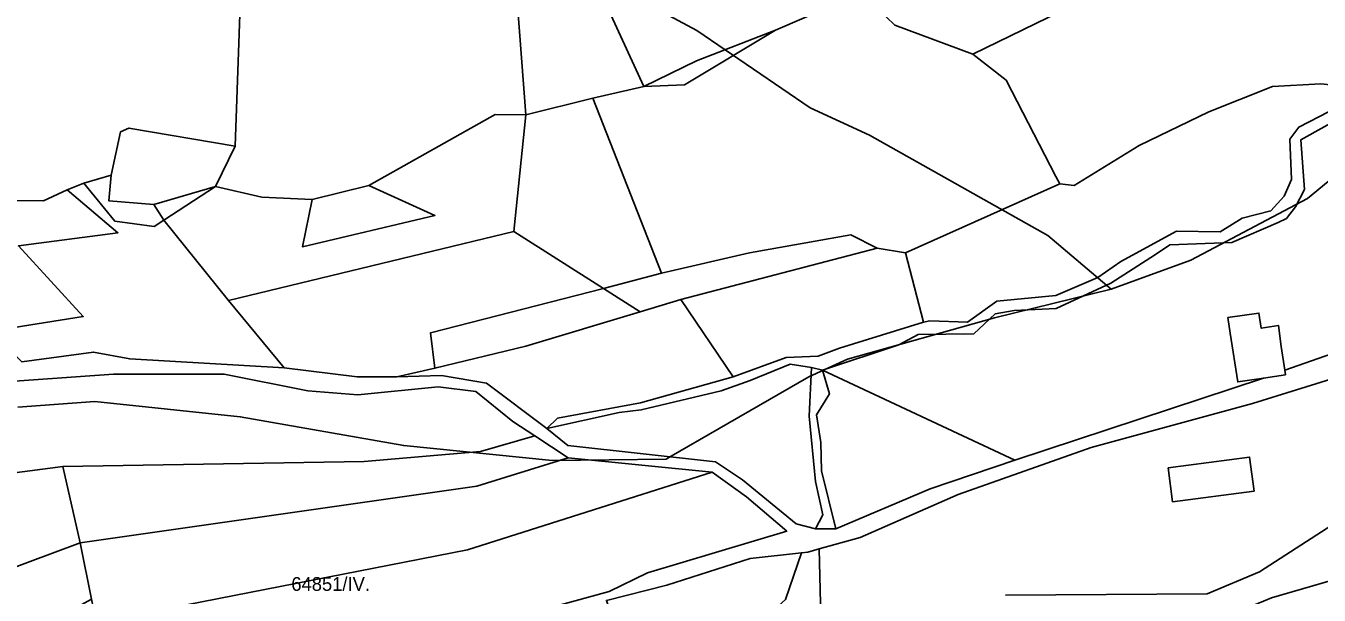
# Model space of a CAD drawing. Extents: x -521261 to -517465, y -1182764 to -1179456.
# Drawn here: x -520234.1 to -519763.3, y -1181096.5 to -1180889.1 of the extents above; entities that cross this region are included whole.
import ezdxf

# ---------------------------------------------------------------- set-up
doc = ezdxf.new("R2010")
doc.units = 0
for name, color, linetype in [('95610013', 7, 'Continuous'), ('95620013', 7, 'Continuous'), ('95630013', 7, 'Continuous'), ('95640013', 7, 'Continuous'), ('95660013', 7, 'Continuous')]:
    doc.layers.add(name, color=color, linetype=linetype)

msp = doc.modelspace()

# ---------------------------------------------------------------- linework, layer by layer
at = {"layer": '95610013'}
for points in [[(-520212.94, -1180946.42), (-520202.96, -1180943.49), (-520203.9, -1180952.83), (-520187.42, -1180954.15), (-520183.85, -1180959.97), (-520187.3, -1180962.26), (-520201.71, -1180960.23)], [(-520260.64, -1180952.48), (-520227.61, -1180952.85), (-520219.04, -1180948.87), (-520200.55, -1180964.48), (-520236.79, -1180969.29), (-520213.15, -1180995.05), (-520246.78, -1181000.33), (-520278.88, -1180969.13), (-520300.29, -1180947.88)], [(-520212.94, -1180946.42), (-520201.71, -1180960.23), (-520187.3, -1180962.26), (-520183.85, -1180959.97), (-520160.25, -1180989.16), (-520140.01, -1181013.64), (-520196.24, -1181010.47), (-520209.39, -1181007.96), (-520235.48, -1181011.57), (-520246.78, -1181000.33), (-520213.15, -1180995.05), (-520236.79, -1180969.29), (-520200.55, -1180964.48), (-520219.04, -1180948.87)], [(-519995.59, -1180988.79), (-519976.54, -1181017.03), (-520010.31, -1181026.46), (-520040.52, -1181031.99), (-520044.41, -1181035.77), (-520066.38, -1181019.3), (-520082.79, -1181016.48), (-520099.06, -1181016.94), (-520085.14, -1181013.84), (-520052.02, -1181005.79), (-520010.45, -1180993.34)], [(-519948.04, -1181013.6), (-519948.9, -1181031.28), (-519946.67, -1181055.07), (-519943.89, -1181067.29), (-519946.57, -1181072.34), (-519953.68, -1181070.49), (-519973.14, -1181054.48), (-519982.97, -1181047.91), (-520036.74, -1181042.02), (-520044.41, -1181035.77), (-520018.1, -1181030.01), (-520010.05, -1181029.02), (-519980.97, -1181022.1), (-519970.37, -1181018.3), (-519955.79, -1181012.41)], [(-519944.01, -1181014.53), (-519874, -1181047.31), (-519904.93, -1181057.82), (-519939.24, -1181072.38), (-519944.44, -1181051.2), (-519944.65, -1181040.94), (-519946.23, -1181030.81), (-519941.52, -1181023.22)], [(-519739.3, -1181085.44), (-519712.94, -1181129.93), (-519700.84, -1181149.53), (-519735.12, -1181160.39), (-519742.39, -1181165.26), (-519775.16, -1181167.72), (-519803.6, -1181180.37), (-519840.89, -1181127.16), (-519809.28, -1181109.36), (-519780.6, -1181097.51)]]:
    msp.add_lwpolyline(points, close=True, dxfattribs=at)
at = {"layer": '95620013'}
for points in [[(-520153.4, -1180806.35), (-520157.92, -1180932.93), (-520196.52, -1180926.36), (-520199.57, -1180927.79), (-520202.96, -1180943.49), (-520212.94, -1180946.42), (-520219.04, -1180948.87), (-520227.61, -1180952.85), (-520260.64, -1180952.48), (-520300.29, -1180947.88), (-520344.99, -1180950.96), (-520344.3, -1180943.96), (-520347.18, -1180922.08), (-520360, -1180918.29), (-520377.28, -1180904.27), (-520373.63, -1180892.94), (-520376.27, -1180881.41), (-520440.58, -1180853.57), (-520296.21, -1180829.93)], [(-520199.57, -1180927.79), (-520196.52, -1180926.36), (-520157.92, -1180932.93), (-520165.05, -1180947.64), (-520187.42, -1180954.15), (-520203.9, -1180952.83), (-520202.96, -1180943.49)]]:
    msp.add_lwpolyline(points, close=True, dxfattribs=at)
at = {"layer": '95630013'}
msp.add_lwpolyline([(-519752.96, -1180921.13), (-519769.89, -1180930.62), (-519768.62, -1180948.73), (-519771.88, -1180955.04), (-519775.19, -1180959.33), (-519778.17, -1180960.73), (-519795.09, -1180968.03), (-519817.61, -1180968.87), (-519822.81, -1180972.36), (-519839.07, -1180982.9), (-519859, -1180992.12), (-519874.24, -1180992.85), (-519881.2, -1180994.07), (-519889.01, -1181001.36), (-519909.19, -1181001.61), (-519916.32, -1181005.27), (-519944.01, -1181014.53), (-519948.04, -1181013.6), (-519955.79, -1181012.41), (-519970.37, -1181018.3), (-519980.97, -1181022.1), (-520010.05, -1181029.02), (-520018.1, -1181030.01), (-520044.41, -1181035.77), (-520040.52, -1181031.99), (-520010.31, -1181026.46), (-519976.54, -1181017.03), (-519957.3, -1181009.97), (-519945.7, -1181009.39), (-519937.88, -1181006.53), (-519907.35, -1180997.12), (-519905.05, -1180996.64), (-519891.34, -1180997.12), (-519880.65, -1180989.37), (-519859.13, -1180987.38), (-519843.84, -1180980.85), (-519835.41, -1180974.97), (-519815.24, -1180963.96), (-519799.37, -1180964.18), (-519791.36, -1180959.21), (-519780.85, -1180956.47), (-519776, -1180951.23), (-519773.4, -1180945.12), (-519773.93, -1180930.43), (-519770.71, -1180926.01), (-519756.06, -1180918.46)], dxfattribs=at)
for points in [[(-519944.01, -1181014.53), (-519941.52, -1181023.22), (-519946.23, -1181030.81), (-519944.65, -1181040.94), (-519944.44, -1181051.2), (-519939.24, -1181072.38), (-519942.24, -1181072.32), (-519946.57, -1181072.34), (-519943.89, -1181067.29), (-519946.67, -1181055.07), (-519948.9, -1181031.28), (-519948.04, -1181013.6)], [(-519970.42, -1181083.14), (-519951.75, -1181081.08), (-519957.49, -1181098.06), (-519974.19, -1181113.01), (-519981.67, -1181128.85), (-520009.75, -1181138.53), (-520022.75, -1181098.44), (-520000.75, -1181092.9)], [(-519949.41, -1181080.84), (-519945.25, -1181079.6), (-519944.34, -1181119.43), (-519981.67, -1181128.85), (-519974.19, -1181113.01), (-519957.49, -1181098.06), (-519951.75, -1181081.08)]]:
    msp.add_lwpolyline(points, close=True, dxfattribs=at)
at = {"layer": '95640013'}
for points in [[(-520075.86, -1180795.03), (-520062.43, -1180839.83), (-520055.89, -1180870.36), (-520052.08, -1180921.54), (-520063.22, -1180921.42), (-520109.27, -1180947.28), (-520129.83, -1180952.33), (-520148.15, -1180951.58), (-520165.05, -1180947.64), (-520157.92, -1180932.93), (-520153.4, -1180806.35)], [(-520075.86, -1180795.03), (-520054.72, -1180801.07), (-520044.44, -1180834.39), (-520009.14, -1180911.27), (-520027.64, -1180915.53), (-520052.08, -1180921.54), (-520055.89, -1180870.36), (-520062.43, -1180839.83)], [(-519944.79, -1180803.65), (-519895.53, -1180797.23), (-519830.34, -1180816.46), (-519820.97, -1180866.09), (-519889.4, -1180899.42), (-519917.75, -1180888.83), (-519929.88, -1180877.1), (-519932.71, -1180837.71), (-519936.58, -1180818.81)], [(-519957.95, -1180803.28), (-519944.79, -1180803.65), (-519936.58, -1180818.81), (-519932.71, -1180837.71), (-519929.88, -1180877.1), (-519961.16, -1180890.66), (-519989.88, -1180901.85), (-520009.14, -1180911.27), (-520044.44, -1180834.39), (-520054.72, -1180801.07), (-520000.15, -1180806.24)], [(-519917.75, -1180888.83), (-519889.4, -1180899.42), (-519877.24, -1180908.93), (-519859.11, -1180944.04), (-519857.68, -1180946.63), (-519913.83, -1180971.76), (-519924.17, -1180970.12), (-519933.74, -1180965.29), (-519970.64, -1180971.8), (-520002.63, -1180979.16), (-520027.64, -1180915.53), (-520009.14, -1180911.27), (-519994.33, -1180910.58), (-519961.16, -1180890.66), (-519929.88, -1180877.1)], [(-519989.88, -1180901.85), (-519961.16, -1180890.66), (-519994.33, -1180910.58), (-520009.14, -1180911.27)], [(-519780.23, -1180911.25), (-519762.65, -1180910.2), (-519750.97, -1180911.49), (-519756.06, -1180918.46), (-519770.71, -1180926.01), (-519773.93, -1180930.43), (-519773.4, -1180945.12), (-519776, -1180951.23), (-519780.85, -1180956.47), (-519791.36, -1180959.21), (-519799.37, -1180964.18), (-519815.24, -1180963.96), (-519835.41, -1180974.97), (-519843.84, -1180980.85), (-519859.13, -1180987.38), (-519880.65, -1180989.37), (-519891.34, -1180997.12), (-519905.05, -1180996.64), (-519907.35, -1180997.12), (-519913.83, -1180971.76), (-519857.68, -1180946.63), (-519852.45, -1180947.32), (-519828.85, -1180932.73), (-519803.42, -1180920.5)], [(-520052.08, -1180921.54), (-520027.64, -1180915.53), (-520002.63, -1180979.16), (-520023.78, -1180984.86), (-520056.43, -1180964.1)], [(-520063.22, -1180921.42), (-520052.08, -1180921.54), (-520056.43, -1180964.1), (-520160.25, -1180989.16), (-520183.85, -1180959.97), (-520165.05, -1180947.64), (-520148.15, -1180951.58), (-520129.83, -1180952.33), (-520133.36, -1180969.6), (-520085.16, -1180958.21), (-520109.27, -1180947.28)], [(-520165.05, -1180947.64), (-520183.85, -1180959.97), (-520187.42, -1180954.15)], [(-520129.83, -1180952.33), (-520109.27, -1180947.28), (-520085.16, -1180958.21), (-520133.36, -1180969.6)], [(-520023.78, -1180984.86), (-520086.73, -1181000.94), (-520085.14, -1181013.84), (-520099.06, -1181016.94), (-520113.5, -1181017.01), (-520140.01, -1181013.64), (-520160.25, -1180989.16), (-520056.43, -1180964.1)], [(-519933.74, -1180965.29), (-519924.17, -1180970.12), (-519995.59, -1180988.79), (-520010.45, -1180993.34), (-520023.78, -1180984.86), (-520002.63, -1180979.16), (-519970.64, -1180971.8)], [(-519924.17, -1180970.12), (-519913.83, -1180971.76), (-519907.35, -1180997.12), (-519937.88, -1181006.53), (-519945.7, -1181009.39), (-519957.3, -1181009.97), (-519976.54, -1181017.03), (-519995.59, -1180988.79)], [(-520010.45, -1180993.34), (-520052.02, -1181005.79), (-520085.14, -1181013.84), (-520086.73, -1181000.94), (-520023.78, -1180984.86)], [(-519785.2, -1180993.74), (-519784.38, -1180999.31), (-519778.1, -1180998.26), (-519777.08, -1181005.97), (-519775.78, -1181014.56), (-519775.53, -1181016.2), (-519783.56, -1181017.44), (-519788.58, -1181018.18), (-519792.93, -1181018.84), (-519795.63, -1181001.04), (-519796.49, -1180995.38)], [(-519727.01, -1181007.89), (-519721.82, -1181010.41), (-519720.05, -1181017.36), (-519694.53, -1181072.36), (-519739.3, -1181085.44), (-519780.6, -1181097.51), (-519809.28, -1181109.36), (-519944.34, -1181119.43), (-519945.25, -1181079.6), (-519930.37, -1181075.45), (-519894.68, -1181059.82), (-519846.27, -1181042.69), (-519787.58, -1181026.69)], [(-520161.81, -1181016.06), (-520131.4, -1181022.11), (-520113.26, -1181023.55), (-520083.95, -1181020.65), (-520070.28, -1181022.36), (-520056.82, -1181033.22), (-520048.82, -1181038.46), (-520068.56, -1181044.19), (-520110.95, -1181047.78), (-520220.57, -1181049.61), (-520239.97, -1181052.18), (-520253.94, -1181048.36), (-520277.6, -1181032.76), (-520278.14, -1181023.43), (-520262.27, -1181020.23), (-520202.17, -1181016.05)], [(-520277.6, -1181032.76), (-520253.94, -1181048.36), (-520239.97, -1181052.18), (-520220.57, -1181049.61), (-520214.23, -1181077.46), (-520289.13, -1181105.34), (-520281.95, -1181113.37), (-520272.96, -1181130.65), (-520279.13, -1181132.17), (-520305.16, -1181142.6), (-520319.71, -1181150.12), (-520336.76, -1181157.91), (-520335.2, -1181068.61), (-520331.46, -1181067.2), (-520328.37, -1181062.33), (-520315.05, -1181055.77), (-520311.25, -1181044.99), (-520301.71, -1181034.37), (-520284.69, -1181029.91)], [(-520068.56, -1181044.19), (-520048.82, -1181038.46), (-520036.68, -1181046.43), (-520069.91, -1181056.82), (-520214.23, -1181077.46), (-520220.57, -1181049.61), (-520110.95, -1181047.78)], [(-519984.22, -1181051.71), (-520073.26, -1181079.95), (-520181.15, -1181101.08), (-520208.33, -1181106.65), (-520210.11, -1181097.99), (-520214.23, -1181077.46), (-520069.91, -1181056.82), (-520036.68, -1181046.43)], [(-519818.28, -1181050.1), (-519788.63, -1181046.2), (-519786.99, -1181058.58), (-519816.62, -1181062.45)], [(-519818.28, -1181050.1), (-519816.62, -1181062.45), (-519786.99, -1181058.58), (-519788.63, -1181046.2)], [(-519984.22, -1181051.71), (-519971.7, -1181060.63), (-519957.06, -1181073.24), (-520007.71, -1181088.34), (-520021.78, -1181095.18), (-520070.4, -1181108.55), (-520084.62, -1181113.41), (-520189.15, -1181149.27), (-520192.88, -1181124.68), (-520181.15, -1181101.08), (-520073.26, -1181079.95)], [(-520210.11, -1181097.99), (-520243.42, -1181116.34), (-520272.96, -1181130.65), (-520281.95, -1181113.37), (-520289.13, -1181105.34), (-520214.23, -1181077.46)]]:
    msp.add_lwpolyline(points, close=True, dxfattribs=at)
for points in [[(-519762.65, -1180910.2), (-519780.23, -1180911.25), (-519803.42, -1180920.5), (-519828.85, -1180932.73), (-519852.45, -1180947.32), (-519857.68, -1180946.63), (-519859.11, -1180944.04), (-519877.24, -1180908.93), (-519889.4, -1180899.42), (-519820.97, -1180866.09), (-519830.34, -1180816.46), (-519754.46, -1180828.52)], [(-519739.37, -1181001.84), (-519775.78, -1181014.56), (-519777.08, -1181005.97), (-519778.1, -1180998.26), (-519784.38, -1180999.31), (-519785.2, -1180993.74), (-519796.49, -1180995.38), (-519795.63, -1181001.04), (-519792.93, -1181018.84), (-519788.58, -1181018.18), (-519783.56, -1181017.44), (-519874, -1181047.31), (-519944.01, -1181014.53), (-519916.32, -1181005.27), (-519909.19, -1181001.61), (-519889.01, -1181001.36), (-519881.2, -1180994.07), (-519874.24, -1180992.85), (-519859, -1180992.12), (-519839.07, -1180982.9), (-519822.81, -1180972.36), (-519817.61, -1180968.87), (-519795.09, -1180968.03), (-519778.17, -1180960.73), (-519775.19, -1180959.33), (-519771.88, -1180955.04), (-519768.62, -1180948.73), (-519769.89, -1180930.62), (-519752.96, -1180921.13)], [(-520235.48, -1181011.57), (-520209.39, -1181007.96), (-520196.24, -1181010.47), (-520140.01, -1181013.64), (-520113.5, -1181017.01), (-520099.06, -1181016.94), (-520082.79, -1181016.48), (-520066.38, -1181019.3), (-520044.41, -1181035.77), (-520036.74, -1181042.02), (-519982.97, -1181047.91), (-519973.14, -1181054.48), (-519953.68, -1181070.49), (-519946.57, -1181072.34), (-519942.24, -1181072.32), (-519939.24, -1181072.38), (-519904.93, -1181057.82), (-519874, -1181047.31), (-519783.56, -1181017.44), (-519775.53, -1181016.2), (-519775.78, -1181014.56), (-519739.37, -1181001.84)], [(-519727.01, -1181007.89), (-519787.58, -1181026.69), (-519846.27, -1181042.69), (-519894.68, -1181059.82), (-519930.37, -1181075.45), (-519945.25, -1181079.6), (-519949.41, -1181080.84), (-519951.75, -1181081.08), (-519970.42, -1181083.14), (-520000.75, -1181092.9), (-520022.75, -1181098.44)], [(-520070.4, -1181108.55), (-520021.78, -1181095.18), (-520007.71, -1181088.34), (-519957.06, -1181073.24), (-519971.7, -1181060.63), (-519984.22, -1181051.71), (-520036.68, -1181046.43), (-520048.82, -1181038.46), (-520056.82, -1181033.22), (-520070.28, -1181022.36), (-520083.95, -1181020.65), (-520113.26, -1181023.55), (-520131.4, -1181022.11), (-520161.81, -1181016.06), (-520202.17, -1181016.05), (-520262.27, -1181020.23)]]:
    msp.add_lwpolyline(points, dxfattribs=at)
at = {"layer": '95660013'}
msp.add_lwpolyline([(-520153.4, -1180806.35), (-520152.8, -1180789.67), (-520080.76, -1180777.95), (-520075.86, -1180795.03), (-520062.43, -1180839.83), (-520055.89, -1180870.36), (-520052.08, -1180921.54), (-520063.22, -1180921.42), (-520109.27, -1180947.28), (-520129.83, -1180952.33), (-520148.15, -1180951.58), (-520165.05, -1180947.64), (-520157.92, -1180932.93)], close=True, dxfattribs=at)
for points in [[(-520153.4, -1180806.35), (-520157.92, -1180932.93), (-520165.05, -1180947.64), (-520187.42, -1180954.15), (-520203.9, -1180952.83), (-520202.96, -1180943.49), (-520212.94, -1180946.42), (-520219.04, -1180948.87), (-520227.61, -1180952.85), (-520260.64, -1180952.48), (-520300.29, -1180947.88), (-520344.99, -1180950.96), (-520344.3, -1180943.96), (-520347.18, -1180922.08), (-520360, -1180918.29), (-520377.28, -1180904.27), (-520380.19, -1180902.05), (-520391.57, -1180893.1), (-520413.63, -1180886.67)], [(-520413.63, -1180886.67), (-520391.57, -1180893.1), (-520380.19, -1180902.05), (-520377.28, -1180904.27), (-520360, -1180918.29), (-520347.18, -1180922.08), (-520344.3, -1180943.96), (-520344.99, -1180950.96), (-520300.29, -1180947.88), (-520260.64, -1180952.48), (-520227.61, -1180952.85), (-520219.04, -1180948.87), (-520212.94, -1180946.42), (-520202.96, -1180943.49), (-520203.9, -1180952.83), (-520187.42, -1180954.15), (-520165.05, -1180947.64), (-520148.15, -1180951.58), (-520129.83, -1180952.33), (-520109.27, -1180947.28), (-520063.22, -1180921.42), (-520052.08, -1180921.54), (-520055.89, -1180870.36)], [(-520000, -1180885.4), (-519989.85, -1180890.87), (-519948.5, -1180919), (-519927, -1180929), (-519862, -1180965.5), (-519839, -1180985), (-519881.5, -1180995.5), (-519935, -1181010.5), (-519949, -1181017), (-520000, -1181046.42), (-520001, -1181047), (-520042.5, -1181047.5), (-520096.5, -1181042), (-520156, -1181031.5), (-520209, -1181026), (-520237, -1181028)], [(-519739.5, -1180929), (-519767.5, -1180952), (-519810, -1180974.5), (-519839, -1180985), (-519862, -1180965.5), (-519927, -1180929), (-519948.5, -1180919), (-519989.85, -1180890.87), (-520000, -1180885.4)], [(-520237, -1181028), (-520209, -1181026), (-520156, -1181031.5), (-520096.5, -1181042), (-520042.5, -1181047.5), (-520001, -1181047), (-520000, -1181046.42), (-519949, -1181017), (-519935, -1181010.5), (-519881.5, -1180995.5), (-519839, -1180985), (-519810, -1180974.5), (-519767.5, -1180952), (-519739.5, -1180929)], [(-519877.5, -1181096.5), (-519804, -1181096), (-519785, -1181088), (-519741.5, -1181060)], [(-519741.5, -1181060), (-519785, -1181088), (-519804, -1181096), (-519877.5, -1181096.5)]]:
    msp.add_lwpolyline(points, dxfattribs=at)

# ---------------------------------------------------------------- texts
msp.add_text('64851/IV.', height=5, rotation=0, dxfattribs=at).set_placement((-520137.42, -1181094.93))

doc.saveas('drawing.dxf')
